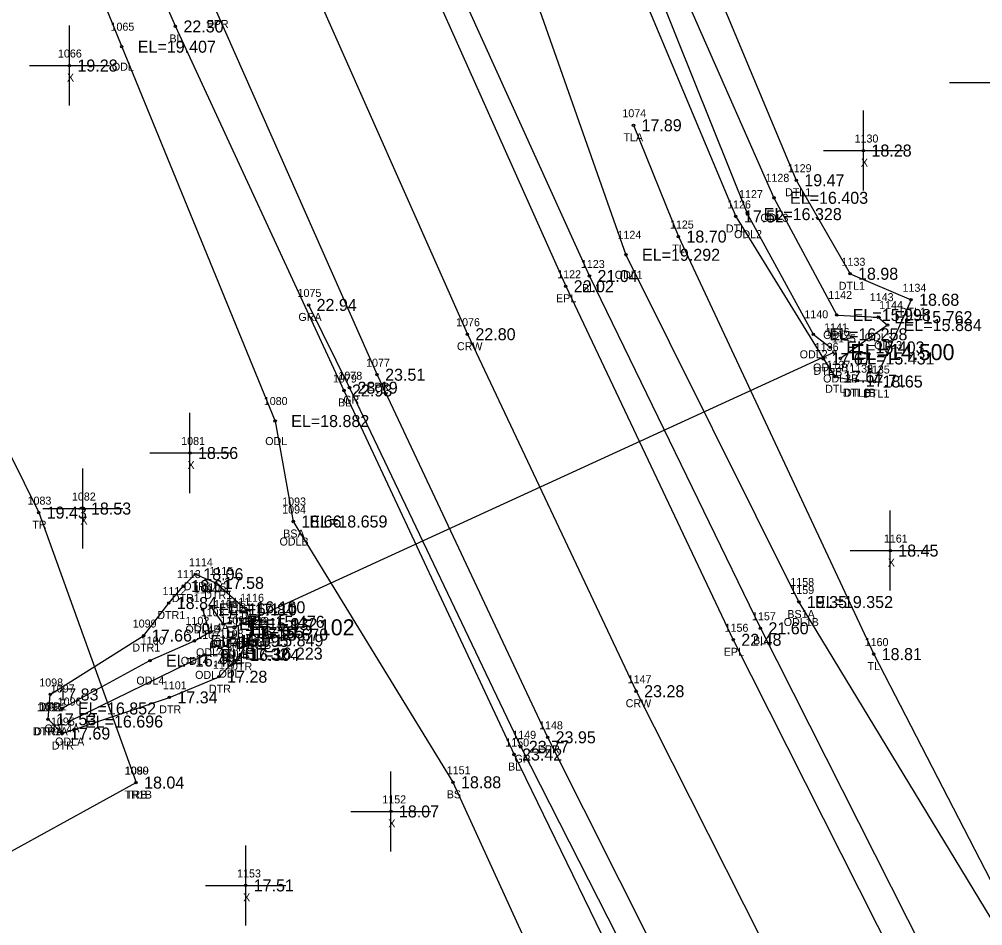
# Model space of a CAD drawing. Extents: x 2042211 to 2045853, y 303080 to 309569.
# Drawn here: x 2042953.4 to 2043073.7, y 306488.1 to 306601.3 of the extents above; entities that cross this region are included whole.
import ezdxf

# ---------------------------------------------------------------- set-up
doc = ezdxf.new("R2010")
doc.units = 0
for name, color, linetype in [('BR_500YR_SCOUR', 7, 'Continuous'), ('RD_DTM_BkLn1', 7, 'Continuous'), ('RD_DTM_BkLn2', 7, 'Continuous'), ('RD_DTM_BkLn_txCode', 7, 'Continuous'), ('RD_EX_DR_Pipe_txCode', 7, 'Continuous'), ('RD_EX_GuardRail_txCode', 7, 'Continuous'), ('RD_EX_H2O', 7, 'Continuous'), ('RD_EX_H2O_txCode', 7, 'Continuous'), ('RD_EX_Misc', 7, 'Continuous'), ('RD_EX_Misc_txCode', 7, 'Continuous'), ('RD_EX_Road', 7, 'Continuous'), ('RD_EX_Road_txCode', 7, 'Continuous'), ('RD_EX_TX_GuardRail_ELEV', 7, 'Continuous'), ('RD_EX_TX_H2O_ELEV', 7, 'Continuous'), ('RD_EX_TX_Misc_ELEV', 7, 'Continuous'), ('RD_EX_TX_Road_ELEV', 7, 'Continuous'), ('RD_EX_TX_VEG_ELEV', 7, 'Continuous'), ('RD_EX_VEG_txCode', 7, 'Continuous'), ('RD_HC_Survey_ELEV', 7, 'Continuous'), ('RD_HC_Survey_txCode', 7, 'Continuous'), ('RD_SMD_Locator', 7, 'Continuous'), ('RD_TX_Pipe_ElevEX', 7, 'Continuous')]:
    doc.layers.add(name, color=color, linetype=linetype)

msp = doc.modelspace()

# ---------------------------------------------------------------- linework, layer by layer
at = {"layer": 'BR_500YR_SCOUR'}
msp.add_line((2042980.25, 306525.37), (2043055.2, 306559.76), dxfattribs=at)
for points in [[(2042864.25, 306612.56), (2042883.28, 306667.35), (2042906.08, 306641.46), (2042916.37, 306622.92), (2042928.46, 306594.97), (2042955.8, 306539.7), (2042967.97, 306505.97)], [(2043030.11, 306588.1), (2043035.72, 306574.19), (2043060.12, 306522.02), (2043088.59, 306466.9), (2043098.93, 306441.29), (2043120.97, 306400.06), (2043177.31, 306317.21), (2043201.76, 306279.58), (2043229.83, 306237.41), (2043260.65, 306197.8), (2043289.37, 306160.32), (2043322.23, 306122.17), (2043376.5, 306058.9), (2043456.79, 305961.76), (2043477.52, 305946.76)], [(2042989.52, 306565.65), (2042994.63, 306555.31), (2043016.03, 306510.44), (2043038.99, 306465.35), (2043062.42, 306421.45), (2043086.95, 306378), (2043112.8, 306335.35), (2043139.38, 306293.6), (2043167.12, 306252.13), (2043196.01, 306211.01), (2043226.01, 306171.01), (2043257.1, 306132.34), (2043288.76, 306093.67), (2043353.25, 306016.86), (2043419.08, 305941.69), (2043443.37, 305914.98)], [(2042921.36, 306509.48), (2042936.34, 306488.59), (2042967.97, 306505.97)]]:
    msp.add_lwpolyline(points, dxfattribs=at)
for centre, radius in [((2043030.11, 306588.1), 0.15), ((2043035.72, 306574.19), 0.15), ((2042989.52, 306565.65), 0.15), ((2043055.2, 306559.76), 0.2), ((2042994.63, 306555.31), 0.15), ((2042955.8, 306539.7), 0.15), ((2042980.25, 306525.37), 0.2), ((2043060.12, 306522.02), 0.15), ((2043016.03, 306510.44), 0.15), ((2042967.97, 306505.97), 0.15)]:
    msp.add_circle(centre, radius, dxfattribs=at)
at = {"layer": 'RD_DTM_BkLn1'}
for points in [[(2042857.66, 307329.64), (2042861.09, 307281.84), (2042862.27, 307232.19), (2042866.29, 307183.84), (2042870.56, 307134.28), (2042875.48, 307086.26), (2042882.95, 307037.68), (2042891.21, 306988.93), (2042900.82, 306941.19), (2042911.81, 306893.75), (2042924.4, 306846), (2042938.51, 306799.29), (2042953.5, 306752.33), (2042968.09, 306705.62), (2042985.63, 306659.36), (2043004.49, 306613.62), (2043024.61, 306569.26), (2043045.97, 306525.25), (2043068.43, 306480.84), (2043092.42, 306438.64), (2043116.55, 306395.12)], [(2042839.81, 307329.37), (2042840.93, 307280.46), (2042843.39, 307231.17), (2042846.87, 307181.66), (2042851.76, 307132.07), (2042857.83, 307083.36), (2042865.03, 307034.36), (2042873.56, 306985.67), (2042883.71, 306937.59), (2042895.32, 306889.27), (2042908.01, 306841.41), (2042921.81, 306793.88), (2042936.83, 306746.34), (2042953.05, 306699.55), (2042970.36, 306653.6), (2042989.25, 306607.34), (2043009.36, 306561.99), (2043030.44, 306517.39), (2043052.89, 306472.91), (2043076.3, 306429.26), (2043100.43, 306386.21)], [(2042839.17, 307095.11), (2042841.19, 307080.52), (2042848.71, 307031.33), (2042857.64, 306982.34), (2042868.25, 306933.78), (2042879.62, 306884.9), (2042891.37, 306836.61), (2042906.05, 306788.56), (2042920.38, 306740.36), (2042936.3, 306692.68), (2042942.2, 306670.77), (2042952.72, 306646.49), (2042972.88, 306600.44), (2042993.94, 306554.96), (2043015.19, 306509.48), (2043037.06, 306464.5), (2043060.22, 306420.45)]]:
    msp.add_lwpolyline(points, dxfattribs=at)
at = {"layer": 'RD_DTM_BkLn2'}
for points in [[(2042987.61, 306538.59), (2043007.56, 306506.01), (2043028.33, 306460.53), (2043050.91, 306415.64), (2043073.59, 306371.21), (2043099.2, 306325.99), (2043124.31, 306283.78), (2043153.04, 306242.87), (2043181.09, 306199.31), (2043207.98, 306156.79), (2043235.33, 306117.55), (2043266.83, 306075.19), (2043327.05, 305994.64), (2043378.71, 305930.63), (2043399.93, 305923.27), (2043423.07, 305907.81), (2043428.93, 305892.58), (2043442.97, 305892.19)], [(2043050.77, 306528.53), (2043076.88, 306485.5), (2043100.65, 306445.31), (2043124.7, 306399.73), (2043150.39, 306358.68), (2043176.89, 306319.64), (2043207.15, 306280.1), (2043235.9, 306243.12), (2043269.2, 306203.58), (2043298.35, 306167.99), (2043333.27, 306134.3), (2043400.8, 306058.89), (2043462.45, 305984.07), (2043465.98, 305983.25), (2043477.77, 305989.95), (2043480.51, 305990.34), (2043485.87, 305978.76), (2043487.92, 305969.11), (2043488.21, 305955.35)]]:
    msp.add_lwpolyline(points, dxfattribs=at)
at = {"layer": 'RD_EX_H2O'}
for points in [[(2042866.82, 307329.93), (2042876.23, 307282.16), (2042878.43, 307232.86), (2042875.08, 307184.77), (2042887.19, 307136.65), (2042884.32, 307120.02), (2042882.74, 307087.49), (2042892.51, 307039.16), (2042896.41, 306990.42), (2042899.37, 306973.37), (2042910.05, 306942.23), (2042920.75, 306896.67), (2042927.15, 306846.78), (2042945.6, 306801.59), (2042960.32, 306754.61), (2042976.65, 306708.74), (2042994.63, 306662.76), (2043013.3, 306616.98), (2043029.17, 306571.91), (2043050.77, 306528.53)], [(2042812.2, 307117.75), (2042817.66, 307076.99), (2042828.97, 307027.39), (2042840.42, 306978.95), (2042848.44, 306929.66), (2042859.84, 306880.36), (2042873.68, 306831.67), (2042888.54, 306783.43), (2042900.59, 306749.27), (2042902.9, 306733.67), (2042926.04, 306688.21), (2042936.45, 306668.37), (2042947.44, 306643.99), (2042966.18, 306597.91), (2042985.34, 306551.14), (2042987.61, 306538.59)], [(2043013.85, 306668.94), (2043032.46, 306624.31), (2043050.45, 306581.23), (2043057.16, 306569.54), (2043064.79, 306566.29), (2043060.22, 306556.08), (2043058.12, 306556.18)], [(2043012.24, 306668.43), (2043028.39, 306622.73), (2043047.66, 306579.03), (2043055.5, 306564.39), (2043060.69, 306564.12), (2043061.86, 306563.13), (2043055.96, 306558.96)], [(2043006.91, 306666.68), (2043026.37, 306621.86), (2043044.37, 306576.99), (2043052.57, 306561.98), (2043054.71, 306560.34)], [(2043005.73, 306665.97), (2043024.37, 306620.88), (2043042.89, 306576.7), (2043053.84, 306558.91), (2043055.29, 306556.67), (2043058.12, 306556.18)], [(2042956.97, 306513.88), (2042957.25, 306516.98), (2042968.93, 306524.34), (2042972.05, 306528.4), (2042973.86, 306530.52), (2042975.36, 306532), (2042977.92, 306530.92), (2042981.78, 306527.56), (2042982.37, 306524.67)], [(2042958.7, 306515.23), (2042969.7, 306521.22), (2042975.25, 306523.68), (2042977.15, 306524.75), (2042976.3, 306527.61)], [(2042977.35, 306527.87), (2042978.84, 306525.78), (2042979.77, 306526.06)], [(2042956.97, 306513.88), (2042958.72, 306512.1), (2042972.13, 306516.62), (2042978.34, 306519.2), (2042981, 306521.98), (2042982.37, 306524.67)], [(2042959.58, 306513.6), (2042976.59, 306521.93), (2042979.52, 306522.09), (2042979.61, 306523.74), (2042980.2, 306524.46)]]:
    msp.add_lwpolyline(points, dxfattribs=at)
at = {"layer": 'RD_EX_Misc'}
for p, q in [((2042959.64, 306590.56), (2042959.64, 306600.56)), ((2042954.64, 306595.56), (2042964.64, 306595.56)), ((2043069.6, 306593.44), (2043079.6, 306593.44)), ((2043058.84, 306579.94), (2043058.84, 306589.94)), ((2043053.84, 306584.94), (2043063.84, 306584.94)), ((2042974.7, 306542.15), (2042974.7, 306552.15)), ((2042969.7, 306547.15), (2042979.7, 306547.15)), ((2042961.33, 306535.21), (2042961.33, 306545.21)), ((2042956.33, 306540.21), (2042966.33, 306540.21)), ((2043062.19, 306529.96), (2043062.19, 306539.96)), ((2043057.19, 306534.96), (2043067.19, 306534.96)), ((2042999.8, 306497.37), (2042999.8, 306507.37)), ((2042994.8, 306502.37), (2043004.8, 306502.37)), ((2042981.66, 306488.12), (2042981.66, 306498.12)), ((2042976.66, 306493.12), (2042986.66, 306493.12))]:
    msp.add_line(p, q, dxfattribs=at)
at = {"layer": 'RD_EX_Road'}
for points in [[(2042853.31, 307329.44), (2042854.43, 307281.38), (2042857.15, 307232.07), (2042860.27, 307183.35), (2042865.16, 307133.89), (2042871.37, 307085.7), (2042878.53, 307037.13), (2042886.97, 306988.21), (2042897.02, 306940.01), (2042908.28, 306892.66), (2042921.09, 306844.85), (2042934.41, 306798.2), (2042949.37, 306750.96), (2042965.62, 306704.44), (2042983.48, 306658.43), (2043001.91, 306612.18), (2043021.64, 306567.98), (2043042.58, 306523.81), (2043065.05, 306479.23), (2043088.14, 306436.09), (2043112.53, 306392.81)], [(2042895.94, 306837.56), (2042909.76, 306789.89), (2042925.08, 306742.02), (2042941.49, 306695.02), (2042958.75, 306648.66), (2042978.01, 306602.25), (2042998.08, 306556.93), (2043019.38, 306511.63), (2043041.84, 306466.86), (2043065.03, 306422.83)]]:
    msp.add_lwpolyline(points, dxfattribs=at)
at = {"layer": 'RD_SMD_Locator'}
for centre in [(2042972.88, 306600.44), (2042966.18, 306597.91), (2042959.64, 306595.56), (2043058.84, 306584.94), (2043050.45, 306581.23), (2043047.66, 306579.03), (2043042.89, 306576.7), (2043044.37, 306576.99), (2043029.17, 306571.91), (2043024.61, 306569.26), (2043057.16, 306569.54), (2043021.64, 306567.98), (2043064.79, 306566.29), (2043055.5, 306564.39), (2043060.69, 306564.12), (2043061.86, 306563.13), (2043009.36, 306561.99), (2043052.57, 306561.98), (2043054.71, 306560.34), (2043053.84, 306558.91), (2043055.96, 306558.96), (2042998.08, 306556.93), (2043055.29, 306556.67), (2043058.12, 306556.18), (2043058.12, 306556.18), (2043060.22, 306556.08), (2042993.94, 306554.96), (2042985.34, 306551.14), (2042974.7, 306547.15), (2042961.33, 306540.21), (2042987.61, 306538.59), (2042987.61, 306538.59), (2043062.19, 306534.96), (2042975.36, 306532), (2042973.86, 306530.52), (2042977.92, 306530.92), (2042972.05, 306528.4), (2042977.35, 306527.87), (2043050.77, 306528.53), (2043050.77, 306528.53), (2042976.3, 306527.61), (2042981.78, 306527.56), (2042978.84, 306525.78), (2042979.77, 306526.06), (2042968.93, 306524.34), (2042977.15, 306524.75), (2042980.2, 306524.46), (2042982.37, 306524.67), (2042982.37, 306524.67), (2043045.97, 306525.25), (2042975.25, 306523.68), (2042979.61, 306523.74), (2043042.58, 306523.81), (2042976.59, 306521.93), (2042979.52, 306522.09), (2042981, 306521.98), (2042969.7, 306521.22), (2042978.34, 306519.2), (2042957.25, 306516.98), (2043030.44, 306517.39), (2042972.13, 306516.62), (2042958.7, 306515.23), (2042956.97, 306513.88), (2042956.97, 306513.88), (2042959.58, 306513.6), (2042958.72, 306512.1), (2043019.38, 306511.63), (2043015.19, 306509.48), (2042967.97, 306505.97), (2043007.56, 306506.01), (2042999.8, 306502.37), (2042981.66, 306493.12)]:
    msp.add_circle(centre, 0.15, dxfattribs=at)

# ---------------------------------------------------------------- texts
at = {"layer": 'RD_DTM_BkLn_txCode'}
for s, p in [('BL', (2042972.13, 306598.44)), ('1123', (2043023.54, 306570.26)), ('BL1', (2043023.68, 306567.26)), ('1079', (2042992.56, 306555.96)), ('BL', (2042993.19, 306552.96)), ('1094', (2042986.22, 306539.59)), ('BSA', (2042986.34, 306536.59)), ('1159', (2043049.7, 306529.53)), ('1157', (2043044.91, 306526.25)), ('BS1A', (2043049.33, 306526.53)), ('BL1', (2043045.05, 306523.25)), ('1150', (2043014.09, 306510.48)), ('1151', (2043006.78, 306507.01)), ('BL', (2043014.44, 306507.48)), ('BS', (2043006.78, 306504.01))]:
    msp.add_text(s, height=1, dxfattribs=at).set_placement(p)
at = {"layer": 'RD_EX_DR_Pipe_txCode'}
for s, p in [('1146', (2043054.12, 306561.76)), ('PB', (2043054.42, 306556.76)), ('1121', (2042979.47, 306527.37)), ('PA 30RC', (2042977.09, 306522.37))]:
    msp.add_text(s, height=1, dxfattribs=at).set_placement(p)
at = {"layer": 'RD_EX_GuardRail_txCode'}
for s, p in [('1075', (2042988.14, 306566.65)), ('GRA', (2042988.25, 306563.65)), ('1078', (2042993.24, 306556.31)), ('GR', (2042993.85, 306553.31)), ('1149', (2043014.97, 306511.44)), ('GR', (2043015.25, 306508.44))]:
    msp.add_text(s, height=1, dxfattribs=at).set_placement(p)
at = {"layer": 'RD_EX_H2O_txCode'}
for s, p in [('1065', (2042964.77, 306599.91)), ('ODL', (2042964.94, 306594.91)), ('1129', (2043049.38, 306582.23)), ('1128', (2043046.6, 306581.03)), ('1127', (2043043.3, 306578.99)), ('DTL1', (2043049.04, 306579.23)), ('1126', (2043041.81, 306577.7)), ('ODL3', (2043045.97, 306576.03)), ('1124', (2043028.11, 306573.91)), ('DTL', (2043041.65, 306574.7)), ('ODL2', (2043042.67, 306573.99)), ('1133', (2043056.1, 306570.54)), ('ODL1', (2043027.76, 306568.91)), ('DTL1', (2043055.75, 306567.54)), ('1134', (2043063.72, 306567.29)), ('1142', (2043054.44, 306566.39)), ('1143', (2043059.63, 306566.12)), ('1144', (2043060.8, 306565.13)), ('DTL1', (2043063.38, 306564.29)), ('1140', (2043051.46, 306563.98)), ('1141', (2043053.93, 306562.34)), ('ODL3', (2043053.81, 306561.39)), ('1145', (2043054.9, 306560.96)), ('ODL3', (2043059, 306561.12)), ('1136', (2043052.76, 306559.91)), ('ODL3', (2043060.17, 306560.13)), ('ODL2', (2043050.87, 306558.98)), ('ODL2B', (2043052.54, 306557.34)), ('1137', (2043054.23, 306557.67)), ('1138', (2043057.06, 306557.18)), ('1139', (2043057.06, 306557.18)), ('1135', (2043059.15, 306557.08)), ('DTL', (2043052.6, 306556.91)), ('ODL3B', (2043053.8, 306555.96)), ('DTL', (2043054.05, 306554.67)), ('DTL1B', (2043056.24, 306554.18)), ('DTLB', (2043056.41, 306554.18)), ('DTL1', (2043058.81, 306554.08)), ('1080', (2042983.92, 306553.14)), ('ODL', (2042984.1, 306548.14)), ('1093', (2042986.22, 306540.59)), ('ODLB', (2042985.89, 306535.59)), ('1114', (2042974.58, 306533)), ('1115', (2042977.14, 306531.92)), ('1113', (2042973.08, 306531.52)), ('1158', (2043049.7, 306530.53)), ('1112', (2042971.27, 306529.4)), ('DTR1', (2042973.93, 306530)), ('1104', (2042975.19, 306529.61)), ('1105', (2042976.24, 306529.87)), ('DTR1', (2042972.42, 306528.52)), ('DTR1', (2042976.48, 306528.92)), ('1116', (2042980.97, 306528.56)), ('1106', (2042977.71, 306527.78)), ('1111', (2042979.27, 306528.06)), ('DTR1', (2042970.62, 306526.4)), ('1102', (2042974.14, 306525.68)), ('1103', (2042976.04, 306526.75)), ('1109', (2042978.51, 306525.74)), ('1110', (2042979.38, 306526.46)), ('1099', (2042967.55, 306525.34)), ('ODL4B', (2042974.13, 306524.61)), ('ODL4A', (2042975.16, 306524.87)), ('DTR1', (2042980.34, 306525.56)), ('1120', (2042981.26, 306525.67)), ('1119', (2042981.59, 306525.67)), ('ODL1B', (2043048.88, 306525.53)), ('1107', (2042975.49, 306523.93)), ('1108', (2042978.41, 306524.09)), ('DTR1', (2042967.5, 306522.34)), ('1100', (2042968.56, 306523.22)), ('ODL4', (2042977.15, 306522.78)), ('ODL4B', (2042977.61, 306523.06)), ('1118', (2042980.22, 306522.98)), ('DTR1B', (2042980.46, 306522.67)), ('DTRB', (2042980.62, 306522.67)), ('ODL4', (2042975.45, 306521.75)), ('ODLB', (2042978.48, 306521.46)), ('ODL4', (2042973.55, 306520.68)), ('1117', (2042977.56, 306520.2)), ('ODL', (2042978.37, 306520.74)), ('DTR', (2042979.74, 306519.98)), ('ODL', (2042975.34, 306518.93)), ('ODL', (2042978.27, 306519.09)), ('1098', (2042955.87, 306517.98)), ('ODL4', (2042968, 306518.22)), ('1101', (2042971.31, 306517.62)), ('1097', (2042957.31, 306517.23)), ('DTR', (2042977.07, 306517.2)), ('1092', (2042955.59, 306514.88)), ('DTR1', (2042955.82, 306514.98)), ('1091', (2042955.87, 306514.88)), ('1096', (2042958.17, 306515.6)), ('DTR', (2042970.86, 306514.62)), ('1095', (2042957.33, 306513.1)), ('DTR1A', (2042955.05, 306511.88)), ('DTRA', (2042955.22, 306511.88)), ('ODL4A', (2042956.52, 306512.23)), ('DTR', (2042957.45, 306510.1)), ('ODLA', (2042957.85, 306510.6))]:
    msp.add_text(s, height=1, dxfattribs=at).set_placement(p)
at = {"layer": 'RD_EX_Misc_txCode'}
for s, p in [('1066', (2042958.21, 306596.56)), ('X', (2042959.33, 306593.56)), ('1130', (2043057.73, 306585.94)), ('X', (2043058.52, 306582.94)), ('1081', (2042973.6, 306548.15)), ('X', (2042974.39, 306545.15)), ('1082', (2042959.95, 306541.21)), ('X', (2042961.02, 306538.21)), ('1161', (2043061.39, 306535.96)), ('X', (2043061.88, 306532.96)), ('1152', (2042998.73, 306503.37)), ('X', (2042999.48, 306500.37)), ('1153', (2042980.59, 306494.12)), ('X', (2042981.34, 306491.12))]:
    msp.add_text(s, height=1, dxfattribs=at).set_placement(p)
at = {"layer": 'RD_EX_Road_txCode'}
for s, p in [('EPR', (2042976.78, 306600.25)), ('1122', (2043020.58, 306568.98)), ('EPL', (2043020.43, 306565.98)), ('1077', (2042996.7, 306557.93)), ('EPR', (2042996.86, 306554.93)), ('1156', (2043041.49, 306524.81)), ('EPL', (2043041.38, 306521.81)), ('1148', (2043018.31, 306512.63)), ('EPR', (2043018.15, 306509.63))]:
    msp.add_text(s, height=1, dxfattribs=at).set_placement(p)
at = {"layer": 'RD_EX_TX_GuardRail_ELEV'}
for s, p in [('22.94', (2042990.52, 306564.9)), ('23.19', (2042995.63, 306554.56)), ('23.77', (2043017.03, 306509.69))]:
    msp.add_text(s, height=1.5, dxfattribs=at).set_placement(p)
at = {"layer": 'RD_EX_TX_H2O_ELEV'}
for s, p in [('EL=19.407', (2042968.18, 306597.16)), ('19.47', (2043051.45, 306580.48)), ('EL=16.403', (2043049.66, 306578.28)), ('17.52', (2043043.89, 306575.95)), ('EL=16.328', (2043046.37, 306576.24)), ('EL=19.292', (2043031.17, 306571.16)), ('18.98', (2043058.16, 306568.79)), ('18.68', (2043065.79, 306565.54)), ('EL=15.998', (2043057.5, 306563.64)), ('EL=15.762', (2043062.69, 306563.37)), ('EL=15.884', (2043063.86, 306562.38)), ('EL=16.258', (2043054.57, 306561.23)), ('EL=15.403', (2043056.71, 306559.59)), ('17.67', (2043054.84, 306558.16)), ('EL=15.431', (2043057.96, 306558.21)), ('17.61', (2043056.29, 306555.92)), ('17.71', (2043059.12, 306555.43)), ('17.71', (2043059.12, 306555.43)), ('18.65', (2043061.22, 306555.33)), ('EL=18.882', (2042987.34, 306550.39)), ('EL=18.659', (2042989.61, 306537.84)), ('18.06', (2042976.36, 306531.25)), ('17.58', (2042978.92, 306530.17)), ('18.61', (2042974.86, 306529.77)), ('18.84', (2042973.05, 306527.65)), ('EL=19.352', (2043052.77, 306527.78)), ('EL=16.110', (2042978.3, 306526.86)), ('EL=16.160', (2042979.35, 306527.12)), ('17.84', (2042982.78, 306526.81)), ('EL=15.476', (2042981.77, 306525.31)), ('EL=16.155', (2042979.15, 306524)), ('EL=15.932', (2042980.84, 306525.03)), ('17.66', (2042969.93, 306523.59)), ('EL=16.095', (2042977.25, 306522.93)), ('EL=15.849', (2042981.61, 306522.99)), ('EL=15.670', (2042982.2, 306523.71)), ('17.97', (2042983.37, 306523.92)), ('17.97', (2042983.37, 306523.92)), ('EL=16.494', (2042971.7, 306520.47)), ('EL=16.304', (2042978.59, 306521.18)), ('EL=16.223', (2042981.52, 306521.34)), ('17.32', (2042982, 306521.23)), ('17.28', (2042979.34, 306518.45)), ('17.83', (2042958.25, 306516.23)), ('17.34', (2042973.13, 306515.87)), ('EL=16.852', (2042960.7, 306514.48)), ('17.53', (2042957.97, 306513.13)), ('17.53', (2042957.97, 306513.13)), ('EL=16.696', (2042961.58, 306512.85)), ('17.69', (2042959.72, 306511.35))]:
    msp.add_text(s, height=1.5, dxfattribs=at).set_placement(p)
at = {"layer": 'RD_EX_TX_Misc_ELEV'}
for s, p in [('22.30', (2042973.88, 306599.69)), ('19.28', (2042960.64, 306594.81)), ('18.28', (2043059.84, 306584.19)), ('21.04', (2043025.61, 306568.51)), ('22.93', (2042994.94, 306554.21)), ('18.56', (2042975.7, 306546.4)), ('18.53', (2042962.33, 306539.46)), ('18.66', (2042988.61, 306537.84)), ('18.45', (2043063.19, 306534.21)), ('19.35', (2043051.77, 306527.78)), ('21.60', (2043046.97, 306524.5)), ('23.42', (2043016.19, 306508.73)), ('18.88', (2043008.56, 306505.26)), ('18.07', (2043000.8, 306501.62)), ('17.51', (2042982.66, 306492.37))]:
    msp.add_text(s, height=1.5, dxfattribs=at).set_placement(p)
at = {"layer": 'RD_EX_TX_Road_ELEV'}
for s, p in [('22.02', (2043022.64, 306567.23)), ('23.51', (2042999.08, 306556.18)), ('22.48', (2043043.58, 306523.06)), ('23.95', (2043020.38, 306510.88))]:
    msp.add_text(s, height=1.5, dxfattribs=at).set_placement(p)
at = {"layer": 'RD_EX_TX_VEG_ELEV'}
for s, p in [('17.89', (2043031.11, 306587.35)), ('18.70', (2043036.72, 306573.44)), ('19.43', (2042956.8, 306538.95)), ('18.81', (2043061.12, 306521.27)), ('18.04', (2042968.97, 306505.22)), ('18.04', (2042968.97, 306505.22))]:
    msp.add_text(s, height=1.5, dxfattribs=at).set_placement(p)
at = {"layer": 'RD_EX_VEG_txCode'}
for s, p in [('1074', (2043028.72, 306589.1)), ('TLA', (2043028.85, 306586.1)), ('1125', (2043034.66, 306575.19)), ('TL', (2043034.95, 306572.19)), ('1083', (2042954.41, 306540.7)), ('TR', (2042955, 306537.7)), ('1160', (2043058.99, 306523.02)), ('TL', (2043059.34, 306520.02)), ('1090', (2042966.54, 306506.97)), ('1089', (2042966.58, 306506.97)), ('TR1B', (2042966.53, 306503.97)), ('TRB', (2042966.7, 306503.97))]:
    msp.add_text(s, height=1, dxfattribs=at).set_placement(p)
at = {"layer": 'RD_HC_Survey_ELEV'}
for s, p in [('22.80', (2043010.36, 306561.24)), ('23.28', (2043031.44, 306516.64))]:
    msp.add_text(s, height=1.5, dxfattribs=at).set_placement(p)
at = {"layer": 'RD_HC_Survey_txCode'}
for s, p in [('1076', (2043007.95, 306562.99)), ('CRW', (2043008.05, 306559.99)), ('1147', (2043029.38, 306518.39)), ('CRW', (2043029.13, 306515.39))]:
    msp.add_text(s, height=1, dxfattribs=at).set_placement(p)
at = {"layer": 'RD_TX_Pipe_ElevEX'}
for s, p in [('EL=14.500', (2043057.2, 306558.76)), ('EL=15.102', (2042982.25, 306524.37))]:
    msp.add_text(s, height=2, dxfattribs=at).set_placement(p)

doc.saveas('drawing.dxf')
